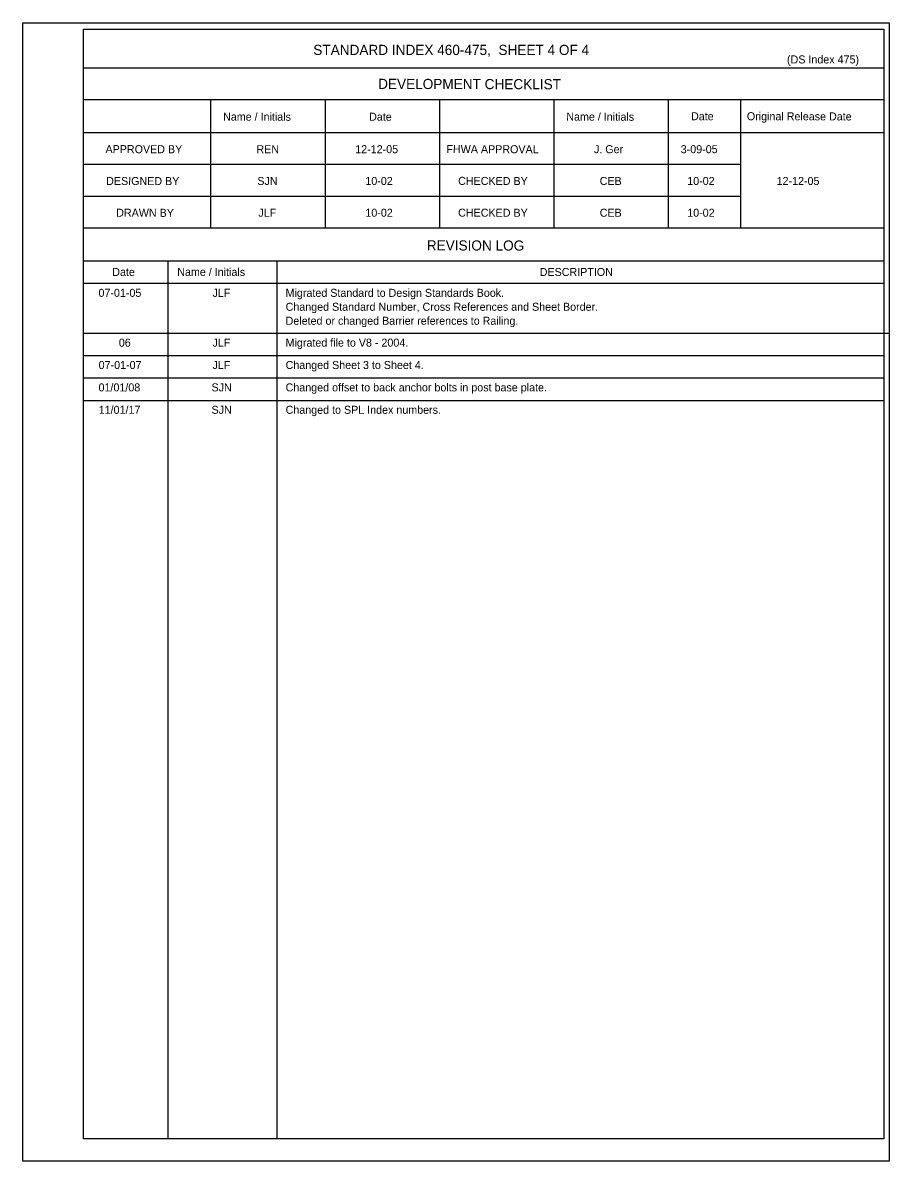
# Model space of a CAD drawing. Extents: x 21587 to 21659.1, y 56113.9 to 56155.9.
# Drawn here: x 21637.29 to 21659.1, y 56124.63 to 56153.3 of the extents above; entities that cross this region are included whole.
import ezdxf

# ---------------------------------------------------------------- set-up
doc = ezdxf.new("R2010")
doc.units = 0
for name, color, linetype in [('Border', 7, 'Continuous'), ('PlotBorder_dp', 7, 'Continuous'), ('SheetBorder_dp', 7, 'Continuous')]:
    doc.layers.add(name, color=color, linetype=linetype)

msp = doc.modelspace()

# ---------------------------------------------------------------- linework, layer by layer
at = {"layer": 'Border'}
for p, q in [((21658.966, 56152.158), (21638.819, 56152.158)), ((21658.966, 56151.358), (21638.819, 56151.358)), ((21642.019, 56151.358), (21642.019, 56148.13)), ((21644.899, 56151.358), (21644.899, 56148.13)), ((21647.779, 56151.358), (21647.779, 56148.13)), ((21650.659, 56151.358), (21650.659, 56148.13)), ((21653.539, 56151.358), (21653.539, 56148.13)), ((21655.354, 56151.358), (21655.354, 56148.13)), ((21658.966, 56150.53), (21638.819, 56150.53)), ((21655.354, 56149.73), (21638.819, 56149.73)), ((21655.354, 56148.93), (21638.819, 56148.93)), ((21658.966, 56148.13), (21638.819, 56148.13)), ((21658.966, 56147.302), (21638.819, 56147.302)), ((21640.94, 56147.302), (21640.94, 56125.196)), ((21643.682, 56147.302), (21643.682, 56125.196)), ((21658.966, 56146.738), (21638.819, 56146.738))]:
    msp.add_line(p, q, dxfattribs=at)
msp.add_lwpolyline([(21638.82, 56153.138), (21658.966, 56153.138), (21658.966, 56125.196), (21638.82, 56125.196)], close=True, dxfattribs=at)
at = {"layer": 'PlotBorder_dp'}
for p, q in [((21638.82, 56145.484), (21659.102, 56145.484)), ((21638.82, 56144.921), (21658.966, 56144.921)), ((21638.82, 56144.357), (21658.966, 56144.357)), ((21638.82, 56143.793), (21658.966, 56143.793)), ((21637.289, 56124.634), (21637.289, 56124.634))]:
    msp.add_line(p, q, dxfattribs=at)
msp.add_lwpolyline([(21637.289, 56153.301), (21659.102, 56153.301), (21659.102, 56124.634), (21637.289, 56124.634)], close=True, dxfattribs=at)

# ---------------------------------------------------------------- texts
at = {"layer": 'SheetBorder_dp'}
for s, height, p in [('STANDARD INDEX 460-475,  SHEET 4 OF 4', 0.256, (21644.603, 56152.49)), ('(DS Index 475)', 0.2016, (21656.529, 56152.277)), ('REN', 0.2016, (21643.171, 56150.017)), ('12-12-05', 0.2016, (21645.659, 56150.017)), ('J. Ger', 0.2016, (21651.669, 56150.017)), ('3-09-05', 0.2016, (21653.853, 56150.017)), ('SJN', 0.2016, (21643.194, 56149.217)), ('10-02', 0.2016, (21645.914, 56149.217)), ('CEB', 0.2016, (21651.814, 56149.217)), ('10-02', 0.2016, (21654.017, 56149.217)), ('12-12-05', 0.2016, (21656.267, 56149.217)), ('JLF', 0.2016, (21643.219, 56148.417)), ('10-02', 0.2016, (21645.914, 56148.417)), ('CEB', 0.2016, (21651.814, 56148.417)), ('10-02', 0.2016, (21654.017, 56148.417)), ('DESCRIPTION', 0.2016, (21650.303, 56146.925)), ('07-01-05', 0.2016, (21639.195, 56146.4)), ('JLF', 0.2016, (21642.066, 56146.4)), ('Migrated Standard to Design Standards Book.', 0.2016, (21643.906, 56146.4)), ('Changed Standard Number, Cross References and Sheet Border.', 0.2016, (21643.906, 56146.049)), ('Deleted or changed Barrier references to Railing.', 0.2016, (21643.906, 56145.697)), ('06', 0.2016, (21639.707, 56145.146)), ('JLF', 0.2016, (21642.066, 56145.146)), ('Migrated file to V8 - 2004.', 0.2016, (21643.906, 56145.146)), ('07-01-07', 0.2016, (21639.199, 56144.583)), ('JLF', 0.2016, (21642.066, 56144.583)), ('Changed Sheet 3 to Sheet 4.', 0.2016, (21643.906, 56144.583)), ('01/01/08', 0.2016, (21639.197, 56144.019)), ('SJN', 0.2016, (21642.041, 56144.019)), ('Changed offset to back anchor bolts in post base plate.', 0.2016, (21643.906, 56144.019)), ('11/01/17', 0.2016, (21639.201, 56143.455)), ('SJN', 0.2016, (21642.041, 56143.455)), ('Changed to SPL Index numbers.', 0.2016, (21643.906, 56143.455))]:
    msp.add_text(s, height=height, dxfattribs=at).set_placement(p)
for s, height, p in [('DEVELOPMENT CHECKLIST', 0.256, (21646.235, 56151.635)), ('Name / Initials', 0.2016, (21642.332, 56150.837)), ('Date', 0.2016, (21646.007, 56150.835)), ('Name / Initials', 0.2016, (21650.972, 56150.837)), ('Date', 0.2016, (21654.112, 56150.847)), ('Original Release Date', 0.2016, (21655.518, 56150.847)), ('APPROVED BY', 0.2016, (21639.371, 56150.019)), ('FHWA APPROVAL', 0.2016, (21647.954, 56150.019)), ('DESIGNED BY', 0.2016, (21639.388, 56149.217)), ('CHECKED BY', 0.2016, (21648.249, 56149.219)), ('DRAWN BY', 0.2016, (21639.641, 56148.417)), ('CHECKED BY', 0.2016, (21648.249, 56148.419)), ('REVISION LOG', 0.256, (21647.46, 56147.569)), ('Date', 0.2016, (21639.542, 56146.926)), ('Name / Initials', 0.2016, (21641.178, 56146.928))]:
    msp.add_text(s, height=height, rotation=359.8756, dxfattribs=at).set_placement(p)

doc.saveas('drawing.dxf')
